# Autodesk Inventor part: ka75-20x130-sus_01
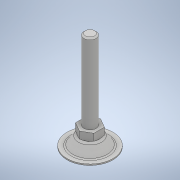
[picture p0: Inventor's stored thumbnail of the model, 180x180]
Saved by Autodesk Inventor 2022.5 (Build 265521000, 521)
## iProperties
Part Number: ka75-20x130-sus_01
Material: 一般
Document SubType Name: Modeling
Designer: ImaoCorp
Density: 1 g/cm^3
Appearance: 既定
Author: ImaoCorp
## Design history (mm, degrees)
feature "ka75-20x130-sus_01"
node "ソリッド1"
